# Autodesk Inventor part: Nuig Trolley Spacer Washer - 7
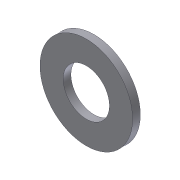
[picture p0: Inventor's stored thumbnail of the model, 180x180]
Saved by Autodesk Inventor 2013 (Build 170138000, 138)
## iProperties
Shininess: 64.0
Length Units: 11269
Angle Units: 11279
Time Units: 11290
Mass Units: 11286
Length Display Precision: 3
Angle Display Precision: 2
Created: 2002-08
Part Number: Nuig Trolley Spacer Washer - 7
Document SubType Name: Modeling
Designer: kalamea
Density: 1 g/cm^3
Material: Generic
Mass: 2.71484 g
Surface Area: 22.8018 cm^2
Volume: 2.71484 cm^3
Density: 0.0
Volumn: 0.0
Area: 0.0
PropertySet Name: Model Information
Control State: 0
Master: False
Checked Out: False
DRAWING NUMBER: ME08-2007-PT
Author: kalamea
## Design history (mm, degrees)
sketch "Sketch1"
  geometry: C1 r 19.05 at (0, 0); C2 r 9.525 at (0, 0); 1 further point
  constraints: 2 centre point, 2 coincident
  dimensions: "d0" = 19.05 diameter of C2; "d1" = 38.1 diameter of C1
extrude "Extrusion1" new body sketch "Sketch1" stored distance "d2" = 3.175; taper "d3" = 0 deg
body "Solid1"
